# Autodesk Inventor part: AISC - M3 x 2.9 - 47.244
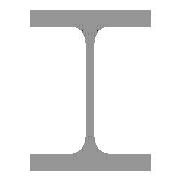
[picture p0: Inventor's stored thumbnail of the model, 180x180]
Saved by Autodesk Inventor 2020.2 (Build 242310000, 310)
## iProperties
Created: 2019-01
Part Number: AISC - M3 x 2.9 - 47.244
Material: Steel, Mild
Description: M-Shape
Document SubType Name: Modeling
Standard: ANSI
Designer: thira
Standards Organization: ANSI
Language: en-US
Size Designation: M3 x 2.9
Categories: <MemberInstance><Categories><Category DisplayName="Structural Shapes" InternalName="089c4875-fa83-4c05-b084-43b9cc11f5ed" Mnemonic="GRDR"><CategoryParameter Dis
Stock Number: M3 x 2.9
Density: 7.85 g/cm^3
Appearance: Semi-Polished
_CCFamilyMember: 14
_CCFamilyDisplayName: ANSI M - M-Shape — Sizes in parentheses have been withdrawn
_FrameMemberDoc: Frame Member File
_Version: 15.0.0
_GetPNFromCC: 1
G_L: 47.154 in
G_W: 2.250 in
G_H: 3.000 in
+232EC5BD-1015-4B71-B393-0886878F9EFE+CUTDETAIL1: Notch
+83DAD992-845A-4DF3-8AC6-8DC18E318CED+CUTDETAIL2: Notch
+7F52A135-0A9E-4B03-A16F-DCDCDF989D45+CUTDETAIL3: Notch
IsCustomPart: 1
Author: thira
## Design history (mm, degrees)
node "Start plane"
node "End plane"
sketch "Sketch"
  geometry: L1 (-28.575, -38.1)-(-28.575, -34.798); L2 (-28.575, -34.798)-(-10.541, -34.798); L3 (-1.143, -25.4)-(-1.143, 0); L4 (-1.143, 0)-(0, 0); L5 (0, 0)-(0, -38.1); L6 (0, -38.1)-(-28.575, -38.1); L7 (-60, 0)-(80, 0); L8 (0, -60)-(0, 80); L9 (28.575, -38.1)-(28.575, -34.798); L10 (28.575, -34.798)-(10.541, -34.798); L11 (0, -38.1)-(28.575, -38.1); L12 (1.143, -25.4)-(1.143, 0); L13 (1.143, 0)-(0, 0); L14 (-28.575, 38.1)-(-28.575, 34.798); L15 (0, 38.1)-(-28.575, 38.1); L16 (0, 38.1)-(28.575, 38.1); L17 (28.575, 34.798)-(10.541, 34.798); L18 (-28.575, 34.798)-(-10.541, 34.798); L19 (1.143, 25.4)-(1.143, 0); L20 (-1.143, 25.4)-(-1.143, 0); L21 (28.575, 38.1)-(28.575, 34.798); L22 (0, 108)-(0, -88) reference; L23 (-88, 0)-(108, 0) reference; A1 r 9.398 centre (-10.541, 25.4) between (-1.143, 25.4) and (-10.541, 34.798); A2 r 9.398 centre (10.541, 25.4) between (10.541, 34.798) and (1.143, 25.4); A3 r 9.398 centre (10.541, -25.4) between (1.143, -25.4) and (10.541, -34.798); A4 r 9.398 centre (-10.541, -25.4) between (-10.541, -34.798) and (-1.143, -25.4); 4 further points
  constraints: 42 end point, 11 symmetric about line, 8 point on circle, 8 point on line, 8 tangent, 4 centre point, 4 collinear, 4 parallel, 3 equal radius, 1 perpendicular, 1 vertical, 13 other
  dimensions: "d1" = 38.1 vertical distance of L1.start L3.end (= 0.5 x G_H); "d2" = 3.302 distance between parallel lines of L2 L6 (= G_T1); "d3" = 28.575 distance from line of L5.end L1 (= 0.5 x G_W); "d4" = 1.143 distance between parallel lines of L5 L3 (= 0.5 x G_T); "d13" = 9.398 radius of A1 (= G_IR)
extrude "Body" new body sketch "Sketch" stored distance "d5" = 1197.714 (= G_L); taper "d6" = 0 deg
node "Driven Length"
  sketch "Sketch4"
    geometry: L1 (0, 0)-(10, 0) reference
    constraints: 2 end point, 1 horizontal
  workplane "Work Plane3"
  sketch "Sketch5"
    geometry: L1 (-2, 0)-(12, 0) reference; L2 (-2, 1200)-(12, 1200) reference
    dimensions: "d15" = 1200 distance between parallel lines of L1 L2 (derived)
workplane "Work Plane4"
workplane "Work Plane5"
workplane "Work Plane6"
sketch "Sketch6"
  geometry: L1 (-28.575, -38.1)-(-28.575, -34.798); L2 (-28.575, -34.798)-(-10.541, -34.798); L3 (-1.143, -25.4)-(-1.143, 0); L4 (-1.143, 25.4)-(-1.143, 0); L5 (-28.575, 34.798)-(-10.541, 34.798); L6 (-28.575, 38.1)-(-28.575, 34.798); L7 (0, 38.1)-(-28.575, 38.1); L8 (0, 38.1)-(28.575, 38.1); L9 (28.575, 38.1)-(28.575, 34.798); L10 (28.575, 34.798)-(10.541, 34.798); L11 (1.143, 25.4)-(1.143, 0); L12 (1.143, -25.4)-(1.143, 0); L13 (28.575, -34.798)-(10.541, -34.798); L14 (28.575, -38.1)-(28.575, -34.798); L15 (0, -38.1)-(28.575, -38.1); L16 (0, -38.1)-(-28.575, -38.1); A1 r 9.398 centre (-10.541, -25.4) between (-10.541, -34.798) and (-1.143, -25.4); A2 r 9.398 centre (-10.541, 25.4) between (-1.143, 25.4) and (-10.541, 34.798); A3 r 9.398 centre (10.541, 25.4) between (10.541, 34.798) and (1.143, 25.4); A4 r 9.398 centre (10.541, -25.4) between (1.143, -25.4) and (10.541, -34.798)
  constraints: 32 end point, 8 point on circle, 4 centre point
extrude "Extrusion2" new body sketch "Sketch6" stored distance "d16" = 3.302; taper "d17" = 0 deg
combine "Combine1"
  body "Solid2"
workplane "Work Plane7"
workplane "Work Plane8"
workplane "Work Plane9"
sketch "Sketch7"
  geometry: L1 (-28.575, -38.1)-(-28.575, -34.798); L2 (-28.575, -34.798)-(-10.541, -34.798); L3 (-1.143, -25.4)-(-1.143, 0); L4 (-1.143, 25.4)-(-1.143, 0); L5 (-28.575, 34.798)-(-10.541, 34.798); L6 (-28.575, 38.1)-(-28.575, 34.798); L7 (0, 38.1)-(-28.575, 38.1); L8 (0, 38.1)-(28.575, 38.1); L9 (28.575, 38.1)-(28.575, 34.798); L10 (28.575, 34.798)-(10.541, 34.798); L11 (1.143, 25.4)-(1.143, 0); L12 (1.143, -25.4)-(1.143, 0); L13 (28.575, -34.798)-(10.541, -34.798); L14 (28.575, -38.1)-(28.575, -34.798); L15 (0, -38.1)-(28.575, -38.1); L16 (0, -38.1)-(-28.575, -38.1); A1 r 9.398 centre (-10.541, -25.4) between (-10.541, -34.798) and (-1.143, -25.4); A2 r 9.398 centre (-10.541, 25.4) between (-1.143, 25.4) and (-10.541, 34.798); A3 r 9.398 centre (10.541, 25.4) between (10.541, 34.798) and (1.143, 25.4); A4 r 9.398 centre (10.541, -25.4) between (1.143, -25.4) and (10.541, -34.798)
  constraints: 32 end point, 8 point on circle, 4 centre point
extrude "Extrusion3" new body sketch "Sketch7" stored distance "d18" = 3.302; taper "d19" = 0 deg
combine "Combine2"
  body "Solid3"
workplane "Work Plane10"
workplane "Work Plane11"
workplane "Work Plane12"
sketch "Sketch8"
  geometry: L1 (-28.575, -38.1)-(-28.575, -34.798); L2 (-28.575, -34.798)-(-10.541, -34.798); L3 (-1.143, -25.4)-(-1.143, 0); L4 (-1.143, 25.4)-(-1.143, 0); L5 (-28.575, 34.798)-(-10.541, 34.798); L6 (-28.575, 38.1)-(-28.575, 34.798); L7 (0, 38.1)-(-28.575, 38.1); L8 (0, 38.1)-(28.575, 38.1); L9 (28.575, 38.1)-(28.575, 34.798); L10 (28.575, 34.798)-(10.541, 34.798); L11 (1.143, 25.4)-(1.143, 0); L12 (1.143, -25.4)-(1.143, 0); L13 (28.575, -34.798)-(10.541, -34.798); L14 (28.575, -38.1)-(28.575, -34.798); L15 (0, -38.1)-(28.575, -38.1); L16 (0, -38.1)-(-28.575, -38.1); A1 r 9.398 centre (-10.541, -25.4) between (-10.541, -34.798) and (-1.143, -25.4); A2 r 9.398 centre (-10.541, 25.4) between (-1.143, 25.4) and (-10.541, 34.798); A3 r 9.398 centre (10.541, 25.4) between (10.541, 34.798) and (1.143, 25.4); A4 r 9.398 centre (10.541, -25.4) between (1.143, -25.4) and (10.541, -34.798)
  constraints: 32 end point, 8 point on circle, 4 centre point
extrude "Extrusion4" new body sketch "Sketch8" stored distance "d20" = 3.302; taper "d21" = 0 deg
combine "Combine3"
  body "Solid4"
body "Solid1"
other parameters: "G_W" = 57.15 [user parameter; used in 1 equation term], "G_H" = 76.2 [user parameter; used in 1 equation term], "G_T" = 2.286 [user parameter; used in 1 equation term], "G_T1" = 3.302 [user parameter; used in 1 equation term], "G_IR" = 9.398 [user parameter; used in 1 equation term], "G_L" = 1197.714 [user parameter; used in 1 equation term], "G_OFFSET_START" = 0 [user parameter; used in 1 equation term], "G_OFFSET_END" = 0 [user parameter; used in 1 equation term], "d11" = 0 (computed from G_OFFSET_START), "d12" = 1200 (= G_OFFSET_END + B_L), "B_L" = 1200 [user parameter; used in 1 equation term], "d14" = 90 deg
